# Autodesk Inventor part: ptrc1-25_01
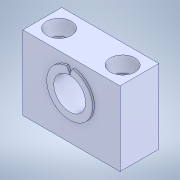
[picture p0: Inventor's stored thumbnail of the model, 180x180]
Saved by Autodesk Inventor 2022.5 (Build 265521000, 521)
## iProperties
Created: 2023-04
Part Number: ptrc1-25_01
Material: Generic
Document SubType Name: Modeling
Designer: ImaoCorp
Density: 1 g/cm^3
Appearance: Default
Author: ImaoCorp
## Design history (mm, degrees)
feature "ptrc1-25_01"
node "ソリッド1"
